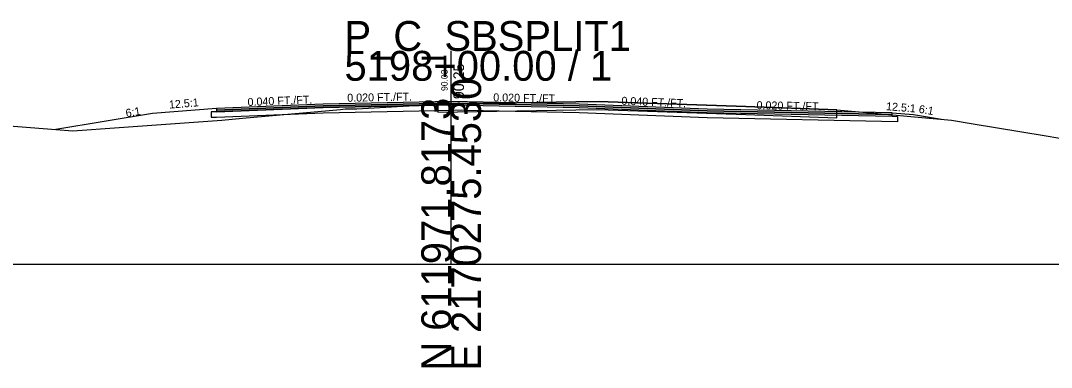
# Model space of a CAD drawing. Extents: x -26 to 1303, y -3010 to 12023.
# Drawn here: x 1109.7 to 1206.2, y 990.3 to 1022.8 of the extents above; entities that cross this region are included whole.
import ezdxf

# ---------------------------------------------------------------- set-up
doc = ezdxf.new("R2010")
doc.units = 0
for name, color, linetype in [('RD_GPK_XS_Cell', 7, 'Continuous'), ('RD_XS_Base', 7, 'Continuous'), ('RD_XS_ExGround', 7, 'Continuous'), ('RD_XS_ExPaveRet', 7, 'Continuous'), ('RD_XS_Greenside', 7, 'Continuous'), ('RD_XS_Pave', 7, 'Continuous'), ('RD_XS_PaveOvlay_CP', 7, 'Continuous'), ('RD_XS_TieSlope', 7, 'Continuous'), ('RD_XS_TX_Elev_EX', 7, 'Continuous'), ('RD_XS_TX_Elev_PR', 7, 'Continuous'), ('RD_XS_TX_ShdSlope', 7, 'Continuous'), ('RD_XS_TX_Slope', 7, 'Continuous')]:
    doc.layers.add(name, color=color, linetype=linetype)

msp = doc.modelspace()

# ---------------------------------------------------------------- linework, layer by layer
at = {"layer": 'RD_GPK_XS_Cell'}
for p, q in [((1150, 1000), (1150, 1020)), ((1000, 1000), (1150, 1000)), ((1150, 1000), (1300, 1000))]:
    msp.add_line(p, q, dxfattribs=at)
at = {"layer": 'RD_XS_Base'}
for p, q in [((1128, 1014.292), (1127.5, 1014.272)), ((1127.5, 1014.272), (1127.5, 1014.272)), ((1127.5, 1014.272), (1127.5, 1013.772)), ((1138, 1014.692), (1128, 1014.292)), ((1128, 1014.292), (1128, 1014.292)), ((1136, 1014.612), (1136, 1014.612)), ((1150, 1014.932), (1138, 1014.692)), ((1138, 1014.192), (1150, 1014.432)), ((1150, 1014.432), (1150, 1015.091)), ((1150, 1015.091), (1150, 1015.091)), ((1150, 1015.091), (1150, 1015.091)), ((1150, 1015.091), (1150, 1014.932)), ((1150, 1014.932), (1150, 1014.932)), ((1150, 1014.932), (1162, 1014.692)), ((1150, 1014.932), (1150, 1014.932)), ((1150, 1014.432), (1150, 1014.932)), ((1150, 1014.932), (1150, 1014.932)), ((1150, 1014.932), (1150, 1014.932)), ((1162, 1014.192), (1150, 1014.432)), ((1150, 1014.432), (1150, 1014.432)), ((1150, 1014.432), (1150, 1014.432)), ((1162, 1014.692), (1162, 1014.692)), ((1162, 1014.692), (1174, 1014.212)), ((1127.5, 1013.772), (1128, 1013.792)), ((1128, 1013.792), (1138, 1014.192)), ((1128, 1013.792), (1128, 1013.792)), ((1136, 1014.112), (1136, 1014.112)), ((1174, 1013.712), (1162, 1014.192)), ((1162, 1014.192), (1162, 1014.192)), ((1174, 1014.212), (1174, 1014.212)), ((1174, 1014.212), (1191.324, 1013.865)), ((1191.824, 1013.355), (1174, 1013.712)), ((1174, 1013.712), (1174, 1013.712)), ((1191.324, 1013.865), (1191.324, 1013.865)), ((1191.324, 1013.865), (1191.824, 1013.855)), ((1191.824, 1013.855), (1191.824, 1013.855)), ((1191.824, 1013.855), (1191.824, 1013.355))]:
    msp.add_line(p, q, dxfattribs=at)
at = {"layer": 'RD_XS_ExGround'}
msp.add_lwpolyline([(1101.842, 1013.501), (1112.962, 1012.617), (1114.536, 1012.485), (1118.894, 1012.809), (1128.507, 1013.505), (1130.436, 1013.689), (1139.623, 1014.495), (1140.075, 1014.552), (1141.167, 1014.575), (1148.759, 1015.007), (1161.671, 1015.218), (1163.809, 1015.253), (1177.613, 1014.776), (1186.132, 1014.483), (1189.259, 1014.199), (1196.883, 1013.501), (1198.926, 1013.156), (1205.569, 1012.077), (1212.919, 1010.798)], dxfattribs=at)
at = {"layer": 'RD_XS_ExPaveRet'}
for points in [[(1177.613, 1014.776), (1163.809, 1015.253), (1163.809, 1015.253), (1161.671, 1015.218), (1161.671, 1015.218), (1148.76, 1015.007), (1148.76, 1015.007), (1148.76, 1014.257), (1148.76, 1014.257), (1148.76, 1014.257), (1161.671, 1014.468), (1161.671, 1014.468), (1163.809, 1014.503), (1163.809, 1014.503), (1177.613, 1014.026), (1177.613, 1014.026), (1186.132, 1013.733), (1186.132, 1014.483), (1186.132, 1014.483), (1177.613, 1014.776), (1177.613, 1014.776)], [(1177.613, 1014.776), (1163.809, 1015.253), (1161.671, 1015.218), (1148.76, 1015.007), (1148.76, 1014.257), (1161.671, 1014.468), (1163.809, 1014.503), (1177.613, 1014.026), (1186.132, 1013.733), (1186.132, 1014.483), (1177.613, 1014.776)]]:
    msp.add_lwpolyline(points, dxfattribs=at)
at = {"layer": 'RD_XS_Greenside'}
for p, q in [((1122, 1014.13), (1112.938, 1012.619)), ((1193.324, 1014.023), (1195.939, 1013.587))]:
    msp.add_line(p, q, dxfattribs=at)
at = {"layer": 'RD_XS_Pave'}
for p, q in [((1150, 1015.25), (1138, 1015.01)), ((1162, 1015.01), (1150, 1015.25)), ((1150, 1015.25), (1150, 1015.25)), ((1150, 1015.25), (1150, 1015.25)), ((1138, 1015.01), (1128, 1014.61)), ((1138, 1014.851), (1128, 1014.451)), ((1128, 1014.451), (1138, 1014.851)), ((1128, 1014.292), (1138, 1014.692)), ((1128, 1014.61), (1128, 1014.61)), ((1128, 1014.61), (1128, 1014.451)), ((1128, 1014.451), (1128, 1014.451)), ((1128, 1014.451), (1128, 1014.292)), ((1136, 1014.93), (1136, 1014.93)), ((1136, 1014.771), (1136, 1014.771)), ((1136, 1014.771), (1136, 1014.771)), ((1136, 1014.612), (1136, 1014.612)), ((1150, 1015.091), (1138, 1014.851)), ((1138, 1014.851), (1150, 1015.091)), ((1138, 1014.692), (1150, 1014.932)), ((1150, 1014.932), (1150, 1015.091)), ((1150, 1015.091), (1150, 1015.091)), ((1150, 1015.091), (1150, 1015.091)), ((1150, 1015.091), (1150, 1015.091)), ((1150, 1015.091), (1150, 1015.091)), ((1150, 1015.091), (1162, 1014.851)), ((1162, 1014.851), (1150, 1015.091)), ((1150, 1015.091), (1150, 1015.091)), ((1150, 1015.091), (1150, 1015.091)), ((1150, 1015.091), (1150, 1015.091)), ((1150, 1015.091), (1150, 1014.932)), ((1150, 1014.932), (1150, 1014.932)), ((1150, 1014.932), (1150, 1014.932)), ((1150, 1014.932), (1150, 1014.932)), ((1150, 1014.932), (1162, 1014.692)), ((1174, 1014.53), (1162, 1015.01)), ((1162, 1015.01), (1162, 1015.01)), ((1162, 1014.851), (1162, 1014.851)), ((1162, 1014.851), (1174, 1014.371)), ((1174, 1014.371), (1162, 1014.851)), ((1162, 1014.851), (1162, 1014.851)), ((1162, 1014.692), (1162, 1014.692)), ((1162, 1014.692), (1174, 1014.212)), ((1191.324, 1014.183), (1174, 1014.53)), ((1174, 1014.53), (1174, 1014.53)), ((1174, 1014.371), (1174, 1014.371)), ((1174, 1014.371), (1191.324, 1014.024)), ((1191.324, 1014.024), (1174, 1014.371)), ((1174, 1014.371), (1174, 1014.371)), ((1174, 1014.212), (1191.324, 1013.865)), ((1174, 1014.212), (1174, 1014.212)), ((1191.324, 1014.024), (1191.324, 1014.183)), ((1191.324, 1014.183), (1191.324, 1014.183)), ((1191.324, 1013.865), (1191.324, 1014.024)), ((1191.324, 1014.024), (1191.324, 1014.024))]:
    msp.add_line(p, q, dxfattribs=at)
at = {"layer": 'RD_XS_PaveOvlay_CP'}
for p, q in [((1150, 1015.25), (1138, 1015.01)), ((1162, 1015.01), (1150, 1015.25)), ((1150, 1015.25), (1150, 1015.25)), ((1150, 1015.25), (1150, 1015.25)), ((1138, 1015.01), (1128, 1014.61)), ((1136, 1014.93), (1136, 1014.93)), ((1174, 1014.53), (1162, 1015.01)), ((1162, 1015.01), (1162, 1015.01)), ((1191.324, 1014.183), (1174, 1014.53)), ((1174, 1014.53), (1174, 1014.53))]:
    msp.add_line(p, q, dxfattribs=at)
at = {"layer": 'RD_XS_TieSlope'}
for p, q in [((1128, 1014.61), (1122, 1014.13)), ((1191.324, 1014.183), (1193.324, 1014.023))]:
    msp.add_line(p, q, dxfattribs=at)

# ---------------------------------------------------------------- texts
at = {"layer": 'RD_GPK_XS_Cell'}
for s, p in [('P_C_SBSPLIT1', (1140, 1020)), ('5198+00.00 / 1', (1140, 1017.2))]:
    msp.add_text(s, height=2.8, dxfattribs=at).set_placement(p)
for s, p in [('E 2170275.4530', (1152.8, 990)), ('N 611971.8173', (1150, 990))]:
    msp.add_text(s, height=2.8, rotation=90, dxfattribs=at).set_placement(p)
at = {"layer": 'RD_XS_TX_Elev_EX'}
msp.add_text('90.03', height=0.6, rotation=90, dxfattribs=at).set_placement((1149.664, 1016.238))
at = {"layer": 'RD_XS_TX_Elev_PR'}
msp.add_text('90.25', height=1, rotation=90, dxfattribs=at).set_placement((1151.204, 1015.467))
at = {"layer": 'RD_XS_TX_ShdSlope'}
for rotation, p in [(4.57392, (1123.587, 1014.584)), (355.42608, (1190.733, 1014.442))]:
    msp.add_text('12.5:1', height=0.75, rotation=rotation, dxfattribs=at).set_placement(p)
at = {"layer": 'RD_XS_TX_Slope'}
for s, rotation, p in [('0.040 FT./FT.', 2.29061, (1130.934, 1014.826)), ('0.020 FT./FT.', 1.14576, (1140.268, 1015.221)), ('0.020 FT./FT.', 358.85424, (1153.939, 1015.27)), ('0.040 FT./FT.', 357.70939, (1165.942, 1014.951)), ('0.020 FT./FT.', 358.85424, (1178.613, 1014.536)), ('6:1', 9.46418, (1119.56, 1013.78)), ('6:1', 350.53582, (1193.778, 1014.202))]:
    msp.add_text(s, height=0.75, rotation=rotation, dxfattribs=at).set_placement(p)

doc.saveas('drawing.dxf')
